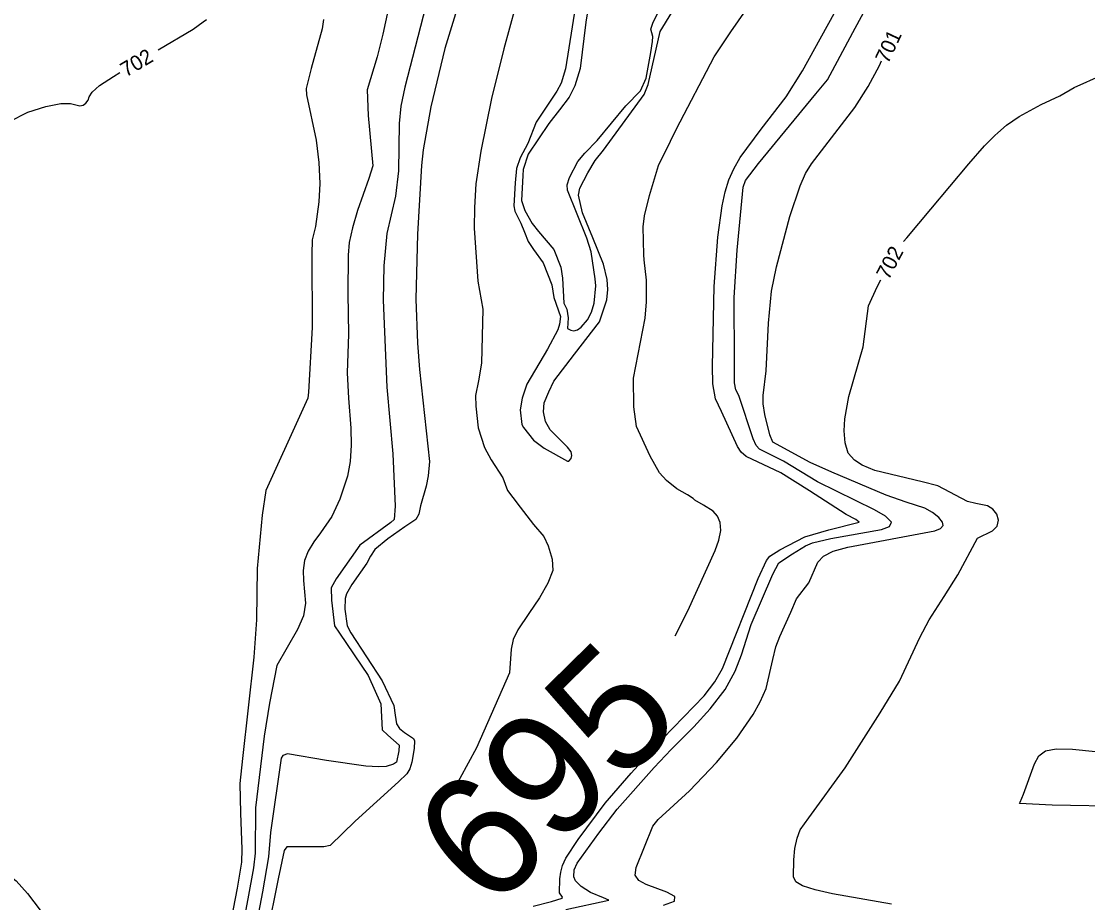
# Model space of a CAD drawing. Extents: x -291892836 to 2945206, y -477993085 to 1832792.
# Drawn here: x 1853584.3 to 1853871.1, y 544921.4 to 545158.4 of the extents above; entities that cross this region are included whole.
import ezdxf

# ---------------------------------------------------------------- set-up
doc = ezdxf.new("R2010")
doc.units = 0
for name, color, linetype in [('DT_X_Contour_Minor', 7, 'Continuous'), ('DT_X_Terrain_Ground_Line', 7, 'Continuous'), ('Level 19', 7, 'Continuous')]:
    doc.layers.add(name, color=color, linetype=linetype)

msp = doc.modelspace()

# ---------------------------------------------------------------- linework, layer by layer
at = {"layer": 'DT_X_Contour_Minor'}
for points in [[(1853770.61, 545087.12), (1853771.63, 545100.36), (1853772.76, 545108.85), (1853773.56, 545112.55), (1853774.58, 545115.85), (1853775.88, 545118.81), (1853777.64, 545121.8), (1853783.3, 545129.4), (1853789.98, 545138.12), (1853794.38, 545145.11), (1853806.25, 545166.65), (1853810.72, 545174.91), (1853817.83, 545189.06), (1853822.64, 545197.23), (1853833.97, 545214.19), (1853835.75, 545216.02), (1853836.74, 545216.73)], [(1853730.77, 544919.63), (1853742.29, 544922.12), (1853740.9, 544922.71), (1853737.38, 544924.14), (1853734.91, 544925.78), (1853733.38, 544927.26), (1853732.93, 544928.4), (1853732.97, 544930.3), (1853733.8, 544932.04), (1853739.64, 544940.13), (1853744.53, 544946.57), (1853754.49, 544957.78), (1853759.04, 544962.64), (1853765.14, 544968.74), (1853769.56, 544973.56), (1853773.55, 544978.75), (1853776.29, 544983.71), (1853777.97, 544988.1), (1853780.58, 544996.25), (1853786.36, 545009.79), (1853788.01, 545012.8), (1853791.7, 545015.26), (1853795.16, 545017.41), (1853797.1, 545018.22), (1853802.01, 545019.36), (1853815.61, 545021.74), (1853817.77, 545022.61), (1853818.27, 545023.79), (1853816.71, 545025.35), (1853813.76, 545027.08), (1853798.4, 545034.63), (1853789.28, 545040.16), (1853782.79, 545043.34), (1853781.96, 545044.36), (1853781.14, 545046.16), (1853777.22, 545057.81), (1853776.49, 545059.38), (1853776.13, 545061.2), (1853776.07, 545066.98), (1853775.99, 545084.2), (1853776.83, 545096.85), (1853778.38, 545113.83), (1853779.07, 545115.66), (1853782.55, 545120.23), (1853797.93, 545138.91), (1853801.07, 545142.73), (1853807.88, 545155.43), (1853815.51, 545169.62)], [(1853760.15, 544993.22), (1853763.51, 544999.89), (1853770.88, 545016.11), (1853771.87, 545018.87), (1853772.43, 545021.51), (1853772.28, 545023.69), (1853771.53, 545025.4), (1853770.39, 545026.7), (1853767.74, 545028.35), (1853765.4, 545029.66), (1853765.02, 545030.15), (1853763.43, 545031.07), (1853760.6, 545032.7), (1853757.85, 545034.92), (1853755.9, 545037.06), (1853753.42, 545041.53), (1853749.79, 545049.51), (1853749.06, 545054.8), (1853748.91, 545062.44), (1853752.07, 545078.61), (1853752.47, 545082.97), (1853752.46, 545088.84), (1853751.84, 545094.3), (1853751.74, 545095.61), (1853751.5, 545103.14), (1853751.94, 545106.16), (1853753.24, 545111.59), (1853755.63, 545119.65), (1853758.87, 545126.25), (1853760.54, 545129.49), (1853770.65, 545148.88), (1853775.11, 545155.65), (1853786.22, 545171.68)], [(1853694.41, 545167.87), (1853687.45, 545140.7), (1853686.39, 545135.64), (1853685.93, 545130.96), (1853685.76, 545118.23), (1853684.94, 545111.44), (1853682.59, 545101.37), (1853681.82, 545092.72), (1853681.66, 545083.48), (1853682.66, 545060.08), (1853684.22, 545042.11), (1853684.89, 545028.02), (1853684.63, 545024.46), (1853683.66, 545023.69), (1853675.36, 545017.6), (1853668.99, 545008.49), (1853667.68, 545006.13), (1853667.76, 545002.76), (1853668.59, 544995.84), (1853669.87, 544993.87), (1853677.62, 544982.55), (1853680.96, 544974.9), (1853681.37, 544967.87), (1853682.9, 544966.45), (1853685.93, 544963.76), (1853685.88, 544962.22), (1853685.24, 544959.19), (1853684.44, 544958.68), (1853682.44, 544958.06), (1853680.37, 544957.93), (1853676.93, 544958.14), (1853666.41, 544959.68), (1853655.89, 544961.44), (1853654.63, 544960.98), (1853654.25, 544960.31), (1853651.31, 544940.32), (1853650.79, 544933.78), (1853649.17, 544924.37), (1853646.8, 544911.58)], [(1853737.79, 545168.66), (1853736.15, 545158.21), (1853734.58, 545145.78), (1853733.17, 545141.09), (1853731.62, 545138.07), (1853729.02, 545134.62), (1853726.18, 545130.98), (1853720.62, 545122.69), (1853719.28, 545118.58), (1853719.21, 545116.96), (1853718.82, 545110.26), (1853719.72, 545107.52), (1853721.68, 545104.07), (1853723.39, 545101.92), (1853727.5, 545097.04), (1853729.42, 545092.3), (1853729.89, 545089.33), (1853730.24, 545082.65), (1853730.98, 545081.01), (1853731.33, 545078.66), (1853731.22, 545075.83), (1853732.11, 545075.39), (1853732.91, 545075.23), (1853733.86, 545075.43), (1853734.86, 545076.15), (1853736.59, 545078.2), (1853737.67, 545080.2), (1853738.38, 545082.6), (1853738.84, 545087.33), (1853738.65, 545089.19), (1853737.6, 545096.44), (1853736.39, 545100.09), (1853731.2, 545113.03)], [(1853702.52, 545165.19), (1853698.18, 545151.15), (1853694.42, 545135.46), (1853692.39, 545123.89), (1853691.98, 545119.7), (1853690.84, 545101.18), (1853690.42, 545083.69), (1853690.83, 545071.91), (1853691.43, 545064.8), (1853694.1, 545040.04), (1853693.75, 545036.21), (1853693.22, 545033.42), (1853691.66, 545028.15), (1853691.21, 545025.88), (1853690.4, 545024.5), (1853687.47, 545022.45), (1853682.85, 545019.23), (1853679.41, 545016.42), (1853678.23, 545014.6), (1853677.24, 545012.75), (1853673.24, 545006.98)], [(1853682.99, 545161.62), (1853681.51, 545154.99), (1853680, 545148.87), (1853677.33, 545140.01), (1853677.64, 545133.1), (1853678.85, 545119.53), (1853677.77, 545116.13), (1853674.76, 545107.55), (1853673.36, 545102.87), (1853672.53, 545098.96), (1853672.18, 545095.59), (1853672.12, 545085.28), (1853672.3, 545074.29), (1853671.95, 545063.87), (1853672.33, 545057.06), (1853672.93, 545049.02), (1853673.02, 545044.47), (1853672.76, 545040.06), (1853672.06, 545036.15), (1853669.97, 545029.89), (1853667.82, 545025.28), (1853664.75, 545020.88), (1853662.96, 545018.47), (1853661.45, 545015.97), (1853660.5, 545013.41), (1853660.11, 545010.77), (1853660.17, 545008.02), (1853660.72, 545002), (1853660.19, 544998.57), (1853658.62, 544994.87), (1853653.05, 544985.18), (1853651.06, 544975.04), (1853649.66, 544966.18), (1853647.34, 544946.95), (1853647.2, 544934.78), (1853646.8, 544930.81), (1853645.28, 544922.46), (1853643.47, 544912.94)], [(1853717.13, 545162.16), (1853714.07, 545151.04), (1853710.73, 545137.67), (1853707.93, 545123.55), (1853706.54, 545114.76), (1853706.16, 545108.39), (1853706.1, 545102.78), (1853707.09, 545088.59), (1853708.41, 545080.99), (1853708.07, 545066.55), (1853707.29, 545061.75), (1853706.45, 545057.82), (1853706.52, 545054.9), (1853707.14, 545049.12), (1853708.87, 545043.81), (1853710.7, 545040.49), (1853713.78, 545035.65), (1853715.07, 545032.25), (1853716.46, 545030.34), (1853718.48, 545027.8), (1853722.06, 545023.09), (1853724.82, 545019.86), (1853726.01, 545017.35), (1853727.1, 545013.79), (1853727.23, 545010.77), (1853725.94, 545007.39)], [(1853733.36, 545162.63), (1853730.68, 545145.68), (1853729.46, 545141.79), (1853728.34, 545139.64), (1853722.8, 545131.31), (1853720.53, 545125.55), (1853718.43, 545121.76), (1853717.51, 545118.89), (1853717.08, 545115.02), (1853716.73, 545108.81), (1853717.05, 545107.35), (1853718.63, 545104.14), (1853719.67, 545101.7), (1853720.64, 545099.19), (1853722.05, 545097.05), (1853724.62, 545093.52), (1853727, 545087.58), (1853727.55, 545084.16), (1853729.31, 545079.08), (1853729.08, 545077.03), (1853728.57, 545075.51), (1853725.86, 545070.24), (1853720.26, 545060.83), (1853718.97, 545057.13), (1853718.5, 545053.92), (1853718.91, 545049.98)], [(1853718.91, 545049.98), (1853719.32, 545049.2), (1853722.01, 545045.78), (1853724.92, 545043.61), (1853731.19, 545040.16), (1853731.55, 545040.13), (1853732.18, 545040.9), (1853732.4, 545041.66), (1853732.15, 545042.69), (1853731.2, 545043.94), (1853726.5, 545048.56), (1853725.31, 545050.8), (1853724.71, 545053.46), (1853724.96, 545055.85), (1853726.16, 545058.81), (1853727.48, 545061.64), (1853733.07, 545068.9), (1853739.81, 545077.65), (1853741.81, 545083.52), (1853742.04, 545086.31), (1853741.83, 545088.99), (1853740.88, 545093.09), (1853738.02, 545100.19), (1853735.23, 545106.96), (1853734.17, 545111.67), (1853734.47, 545113.61), (1853736.67, 545117.7), (1853738.64, 545120.99), (1853740.83, 545123.8), (1853751.78, 545138.74), (1853752.89, 545141.47), (1853756.09, 545155.74), (1853759.25, 545160.81)], [(1853731.2, 545113.03), (1853731.13, 545114.43), (1853731.71, 545116.45), (1853733.97, 545120.77), (1853735.88, 545122.95), (1853739.16, 545126.35), (1853746.89, 545135.71), (1853750.81, 545139.71), (1853752.33, 545143.13), (1853753.6, 545150.07), (1853754.03, 545153.05), (1853754.11, 545154.36), (1853753.58, 545156.36), (1853754.14, 545157.94), (1853755.41, 545160.52)], [(1853621.13, 545150.74), (1853630.56, 545156.31), (1853633.22, 545158.26)], [(1853633.22, 545158.26), (1853634.16, 545158.95)], [(1853665.63, 545158.88), (1853665.25, 545156.39), (1853662.23, 545145.74), (1853660.94, 545140.35), (1853660.99, 545138.67), (1853663.58, 545126.45), (1853664.37, 545120.51), (1853664.57, 545114.84), (1853664.33, 545109.86), (1853663.41, 545103.28), (1853662.55, 545099.69), (1853662.49, 545095.78), (1853662.5, 545076.09), (1853661.52, 545058.71), (1853661.36, 545057.06), (1853659.62, 545053.12), (1853650.08, 545032.24), (1853649.13, 545025.59), (1853647.73, 545011.26), (1853647.58, 544997.47), (1853646.83, 544987.45), (1853643.78, 544960.19), (1853643.12, 544953.47), (1853643.23, 544945.49), (1853643.61, 544935.78), (1853643.51, 544932.28), (1853642.34, 544925.33), (1853639.2, 544909.11)], [(1853756.98, 544920.76), (1853759.99, 544921.85), (1853760.03, 544923.05), (1853757.92, 544924.26), (1853752.3, 544926.35), (1853750.36, 544927.42), (1853749.42, 544928.86), (1853749.63, 544930.88), (1853754.13, 544942.02), (1853755.61, 544943.76), (1853763.98, 544951.52), (1853771.24, 544959.13), (1853776.72, 544965.69), (1853781.11, 544971.99), (1853783.04, 544975.4), (1853784.58, 544979.06), (1853786.43, 544986.8), (1853787.23, 544990.23), (1853788.24, 544993.01), (1853791.28, 544999.55), (1853792.75, 545003.11), (1853796.11, 545007.42), (1853798.53, 545012.97), (1853800.04, 545014.59), (1853802.64, 545015.96), (1853806.58, 545017.04), (1853829.93, 545021.42), (1853831.52, 545022.06), (1853832.21, 545022.81), (1853832.03, 545023.77), (1853831.02, 545025), (1853829.36, 545026.32), (1853827.25, 545027.49), (1853822.27, 545029.1), (1853816.84, 545030.98), (1853802.29, 545037.21), (1853796.45, 545039.79), (1853786.38, 545045.23), (1853785.59, 545047.27), (1853784.26, 545052.69), (1853783.83, 545055.56), (1853783.82, 545057.84), (1853784.63, 545064.43), (1853785.24, 545077.29), (1853786.04, 545085.9), (1853787.38, 545092.38), (1853790.99, 545105.93), (1853793.76, 545114.23), (1853795.22, 545117.48), (1853796.83, 545120.09), (1853808.47, 545135.26), (1853812.04, 545140.9), (1853815.04, 545146.55), (1853815.62, 545147.78)], [(1853581.18, 545131.5), (1853586.09, 545133.97), (1853590.97, 545135.56), (1853595, 545136.31), (1853597.6, 545136.32), (1853600.06, 545135.71), (1853600.94, 545135.89), (1853601.73, 545136.45), (1853602.28, 545137.24), (1853602.61, 545138.17), (1853603.36, 545139.4), (1853605.33, 545141.17), (1853609.09, 545143.63), (1853610.8, 545144.64)], [(1853846.87, 545128.41), (1853849.23, 545130.48), (1853852.63, 545132.86), (1853858.57, 545136.09), (1853863.61, 545138.43), (1853867.4, 545140.63), (1853875.08, 545144.04)], [(1853821.51, 545099.26), (1853822.44, 545100.17), (1853828.85, 545107.95), (1853839.12, 545120.14), (1853843.35, 545124.95), (1853846.06, 545127.71), (1853846.87, 545128.41)], [(1853818.33, 544921.03), (1853802.45, 544923.79), (1853797.76, 544924.88), (1853794.37, 544925.97), (1853792.56, 544927.04), (1853791.92, 544928.37), (1853792.05, 544932.97), (1853792.36, 544936), (1853792.91, 544938.81), (1853793.77, 544940.98), (1853796.1, 544944.28), (1853805.86, 544957.71), (1853815.23, 544972.44), (1853820.47, 544980.99), (1853825.95, 544992.72), (1853828.43, 544997.53), (1853832.43, 545003.72), (1853836.17, 545009.61), (1853841.46, 545019.46), (1853845.47, 545021.43), (1853846.71, 545022.69), (1853847.06, 545024.27), (1853846.61, 545025.91), (1853845.54, 545027.27), (1853844.08, 545028.1), (1853840.97, 545028.74), (1853838.7, 545029.3), (1853830.78, 545033.48), (1853826.54, 545034.64), (1853813.82, 545037.62), (1853810.38, 545039.11), (1853808.34, 545040.39), (1853806.7, 545042.34), (1853805.81, 545045.07), (1853805.57, 545048.28), (1853805.77, 545051.55), (1853806.86, 545057.51), (1853810.67, 545070.93), (1853812.15, 545081.95), (1853814.43, 545087.06), (1853815.4, 545088.91)], [(1853721.97, 544920.46), (1853726.92, 544921.78), (1853729.75, 544922.63), (1853729.82, 544922.92), (1853729.04, 544924.07), (1853729.1, 544927.84), (1853729.36, 544929.67), (1853729.88, 544931.46), (1853730.77, 544933.38), (1853734.02, 544938.39), (1853741.32, 544948.2), (1853748.28, 544956.24), (1853756.8, 544965.59), (1853767.94, 544977.06), (1853770.84, 544980.82), (1853772.83, 544984.44), (1853782.42, 545008.64), (1853784.71, 545013.48), (1853785.6, 545014.59), (1853788.25, 545016.29), (1853795.03, 545019.77), (1853801.48, 545021.67), (1853809.65, 545023.77), (1853808.73, 545024.44), (1853806.1, 545025.79), (1853796.25, 545032.16), (1853788.51, 545036.99), (1853779.2, 545041.41), (1853777.93, 545042.59), (1853776.93, 545044.09), (1853772.61, 545053.53), (1853771.01, 545056.89), (1853770.23, 545060.91), (1853770.14, 545065.74), (1853770.61, 545087.12)], [(1853673.24, 545006.98), (1853671.74, 545004.5), (1853671.38, 545003.26), (1853671.33, 545000.39), (1853671.99, 544995.86), (1853672.96, 544994.03), (1853681.38, 544981.04), (1853684.52, 544974.48), (1853684.85, 544971.82), (1853685.22, 544969.5), (1853686, 544968.3), (1853687.39, 544967.23), (1853689.79, 544965.54), (1853690.1, 544964.93), (1853689.97, 544962.87), (1853689.31, 544959.18), (1853688.76, 544957.41), (1853688.02, 544956.08), (1853685.76, 544953.89), (1853674.14, 544943.31), (1853667.42, 544936.81), (1853665.69, 544936.43), (1853659.83, 544936.41), (1853655.74, 544936.47), (1853655, 544935.49), (1853653.38, 544927.84), (1853650.47, 544913.18)], [(1853725.94, 545007.39), (1853723.65, 545003.37), (1853720.81, 544999.23), (1853717.8, 544994.76), (1853716.62, 544992.18), (1853716.04, 544989.6), (1853715.63, 544983.27), (1853706.7, 544963.02), (1853702.22, 544954.78), (1853701.99, 544954.4)], [(1853881.27, 544947.27), (1853861.54, 544947.67), (1853852.73, 544948.11), (1853852.88, 544948.48), (1853853.77, 544950.62), (1853856.74, 544958.8), (1853857.94, 544960.91), (1853859.7, 544962.24), (1853862.61, 544962.8), (1853866.96, 544962.68), (1853878.45, 544961.55), (1853878.55, 544961.57)], [(1853501.12, 544939.31), (1853513.26, 544933.62), (1853524.44, 544929.01), (1853532.87, 544926.3), (1853538.51, 544925.16), (1853545.4, 544924.91), (1853553.34, 544925.26), (1853558.63, 544926.18), (1853564.44, 544927.09), (1853571.55, 544928.29), (1853577.46, 544929.92), (1853580.18, 544929.45), (1853582.98, 544927.33), (1853585.96, 544923.91), (1853600.19, 544905.28)]]:
    msp.add_lwpolyline(points, dxfattribs=at)

# ---------------------------------------------------------------- texts
at = {"layer": 'DT_X_Terrain_Ground_Line'}
msp.add_text('695', height=33, rotation=44.509, dxfattribs=at).set_placement((1853710.55, 544918.6))
at = {"layer": 'Level 19'}
for s, rotation, p in [('701', 64.813, (1853817.37, 545146.81)), ('702', 30.5558, (1853612.48, 545143.31)), ('702', 62.3607, (1853817.53, 545088.67))]:
    msp.add_text(s, height=4, rotation=rotation, dxfattribs=at).set_placement(p)

doc.saveas('drawing.dxf')
